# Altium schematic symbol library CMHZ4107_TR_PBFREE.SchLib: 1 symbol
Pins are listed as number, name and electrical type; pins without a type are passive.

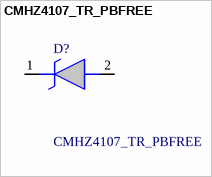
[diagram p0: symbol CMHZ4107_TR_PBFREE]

## CMHZ4107_TR_PBFREE
designator D?
Zener Diodes 500mW 5% Tolerance; Manufacturer_Name: Central Semiconductor; Manufacturer_Part_Number: CMHZ4107 TR PBFREE; Geometry.Height: 1.35mm
footprint SOD3816X135N
pins: 1 K, 2 A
